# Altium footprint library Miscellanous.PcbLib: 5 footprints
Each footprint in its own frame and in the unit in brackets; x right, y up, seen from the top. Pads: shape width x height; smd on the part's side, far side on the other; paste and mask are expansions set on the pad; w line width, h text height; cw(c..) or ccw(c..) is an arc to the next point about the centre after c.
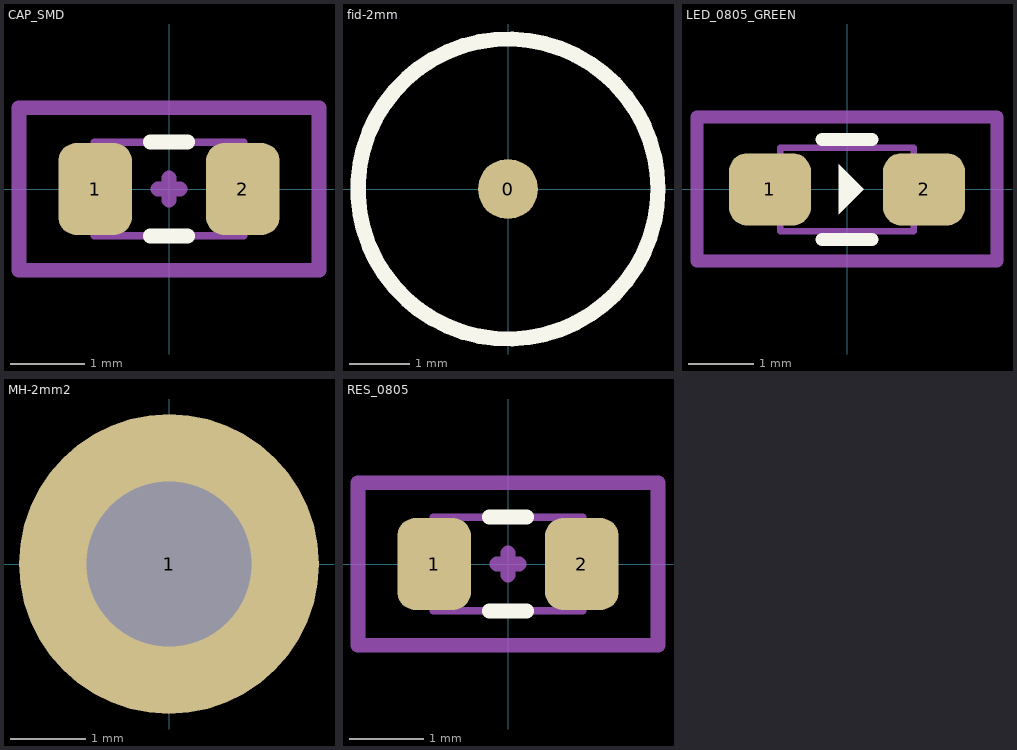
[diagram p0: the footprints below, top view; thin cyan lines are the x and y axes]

## CAP_SMD [mm] "MLCC Capacitor, 0508 Case Size"
height 1.25
pads (2):
  rrect50% 1x1.25 smd: 1(-1,0)
  rrect50% 1x1.25 smd paste+0: 2(1,0)
Top Overlay:
  lines w0.2: -0.254,-0.635 0.254,-0.635 ; -0.254,0.635 0.254,0.635
Mechanical 13:
  lines w0.1: -1.016,-0.635 1.016,-0.635 1.016,0.635 -1.016,0.635 -1.016,-0.635
Component Courtyard:
  lines w0.2: -0.15,0 0.15,0 ; 0,-0.15 0,0.15 ; -2.032,-1.1 2.032,-1.1 2.032,1.1 -2.032,1.1 -2.032,-1.1
3D body "C0805A.STEP": height 0.6, standoff 0, extent -1,-0.625 1,0.625

## fid-2mm [mm]
pads (1):
  round 1 smd mask+1.5: 0(0,0)
Top Overlay:
  circle w0.254: c0,0 r2.5

## LED_0805_GREEN [mm] "Footprint for 0805 Case Size LED"
height 1.1
pads (2):
  rrect50% 1.25x1.1 smd: 1(-1.175,0) 2(1.175,0)
Top Overlay:
  region: -0.127,0.381 -0.127,-0.381 0.254,0
  lines w0.2: -0.381,-0.762 0.381,-0.762 ; -0.381,0.762 0.381,0.762
Mechanical 13:
  lines w0.1: -1.016,-0.635 1.016,-0.635 1.016,0.635 -1.016,0.635 -1.016,-0.635
Component Courtyard:
  lines w0.2: -2.286,-1.094 2.286,-1.094 2.286,1.106 -2.286,1.106 -2.286,-1.094
3D body "Diode_Multicomp_MCL-S270GC_eec.STEP": height 0.8, standoff 0, extent -1.003,-0.625 1.007,0.625

## MH-2mm2 [mm] "2.2mm Mounting hole, non plated"
pads (1):
  round 4 hole 2.2 unplated: 1(0,0)

## RES_0805 [mm] "SMD Resistor, 0805 Case Size"
height 0.8
pads (2):
  rrect50% 1x1.25 smd: 1(-1,0)
  rrect50% 1x1.25 smd paste+0: 2(1,0)
Top Overlay:
  lines w0.2: -0.254,-0.635 0.254,-0.635 ; -0.254,0.635 0.254,0.635
Mechanical 13:
  lines w0.05: -1.016,-0.635 1.016,-0.635 1.016,0.635 -1.016,0.635 -1.016,-0.635
  lines w0.1: -1.016,-0.635 -1.016,0.635 1.016,0.635 1.016,-0.635 -1.016,-0.635
Component Courtyard:
  lines w0.2: -0.15,0 0.15,0 ; 0,-0.15 0,0.15 ; -2.032,-1.1 2.032,-1.1 2.032,1.1 -2.032,1.1 -2.032,-1.1
3D body "R0805.STEP": height 0.5, standoff 0, extent -1,-0.625 1,0.625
